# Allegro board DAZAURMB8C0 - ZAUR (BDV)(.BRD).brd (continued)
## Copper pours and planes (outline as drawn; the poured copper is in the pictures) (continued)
GND on SVCC (solid shape): 122.7,125.97 123.57,124.46 125.2,123.87 131.2,123.87 132.83,124.46 133.7,125.97 149.97,125.97 149.97,82.41 140.88,82.41 137.93,85.36 137.94,85.42 137.83,85.69 137.56,85.8 137.5,85.79 133.26,90.03 133.28,90.09 133.29,90.16 133.17,90.43 132.9,90.54 132.84,90.53 132.78,90.52 128.77,94.53 128.68,94.58 128.59,94.6 126.43,94.6 126.33,94.58 126.25,94.53 125.81,94.09 124.58,94.09 124.44,94.25 124.23,94.31 124.03,94.25 123.89,94.09 120.61,94.09 120.47,94.29 120.25,94.36 120.02,94.29 119.88,94.09 119.58,94.09 119.45,94.31 119.2,94.4 118.96,94.31 118.83,94.09 117.9,94.09 117.41,94.58 117.41,95.49 117.47,95.6 117.49,95.72 117.47,95.84 117.41,95.95 117.41,99.81 117.65,99.94 117.74,100.19 117.65,100.44 117.41,100.57 117.41,101.85 117.63,101.98 117.72,102.22 117.63,102.46 117.41,102.59 117.41,103.82 117.65,103.95 117.74,104.2 117.65,104.45 117.41,104.58 117.41,105.78 117.68,105.89 117.79,106.16 117.68,106.43 117.41,106.54 117.41,108.96 117.53,109.09 117.57,109.26 117.47,109.51 117.21,109.61 117.15,109.61 117.09,109.59 116.65,109.96 116.65,125.97
GND on SVCC (solid shape): outline of 153 points within 26.1,28.56 88.83,93.33
GND on IN3 (solid shape): 108.7,41.18 108.7,36.09 108.82,35.96 108.82,33.82 108.63,33.62 108.63,32.75 105.19,32.75 105.19,35.8 106.89,35.8 107.07,35.98 107.07,40.81 107.24,40.98 107.24,41.36 108.51,41.36
GND on IN3 (solid shape): 105.93,125.97 105.97,125.95 105.98,125.92 105.98,125.65 105.93,125.46 105.98,125.28 105.98,122.85 105.97,122.81 105.93,122.8 102.37,122.8 102.34,122.81 102.34,122.82 102.28,122.91 102.2,122.98 102.18,123 102.17,123.02 102.17,123.89 101.62,124.45 101.62,125.36 102.17,125.92 102.18,125.95 102.22,125.97
GND on IN3 (solid shape): 6.12,11.15 6.1,10.85 6.04,10.56 9.28,7.31 9.28,2.46 10.22,1.52 40.42,1.52 40.48,1.53 40.48,3.28 40.51,3.35 40.58,3.38 40.99,3.46 41.32,3.7 41.43,3.73 41.5,3.63 41.5,1.01 41.35,0.65 41,0.51 4,0.51 1.53,1.53 0.51,4 0.51,10.64 3.23,10.64 4.36,10.18 5.11,11.15 5.11,11.92 6.12,11.92
GND on IN3 (solid shape): 6.89,67.99 8.1,67.1 9.43,67.82 10.53,67.82 8.68,66.12 6.31,66.98 3.12,66.98 3.12,62.76 7.57,62.76 8.17,63.21 8.9,63.36 10.42,63.36 12.59,63.68 13.77,61.84 13.77,61.71 12.76,61.71 12.76,61.84 12.01,62.81 10.88,62.35 8.9,62.35 8.44,62.19 8.17,61.79 8.16,61.75 2.31,61.75 2.11,61.95 2.11,67.79 2.31,67.99
GND on IN3 (solid shape): 12.9,88.91 12.31,87.88 11.2,87.48 8.24,87.48 7.62,86.61 6.6,86.28 5.2,86.28 4.18,86.61 3.56,87.48 3.02,87.48 3.02,86.52 4.12,85.42 6.31,85.42 8.62,86.29 10.49,84.69 10.48,84.6 10.39,84.56 9.44,84.56 8.12,85.31 6.89,84.41 2.21,84.41 2.01,84.61 2.01,87.41 0.51,87.41 0.51,88.29 0.71,88.49 4.49,88.49 4.49,88 4.7,87.5 5.2,87.29 6.6,87.29 7.1,87.5 7.31,88 7.31,88.49 11.2,88.49 11.61,88.62 11.87,88.96 12.85,88.96
GND on IN3 (solid shape): 8.17,47.09 8.44,46.69 8.9,46.53 10.88,46.53 12.01,46.07 12.76,47.04 13.77,47.04 12.59,45.2 10.42,45.52 8.9,45.52 8.17,45.67 7.57,46.12 4.26,46.12 4.26,42.76 7.49,42.76 8.05,43.21 8.75,43.36 10.42,43.36 12.54,43.7 13.77,41.95 13.74,41.87 13.67,41.84 12.76,41.84 12.76,41.89 11.99,42.82 10.88,42.35 8.75,42.35 8.34,42.19 8.14,41.79 8.14,41.75 3.25,41.75 3.25,47.13 8.16,47.13
GND on IN3 (solid shape): 9.14,111.72 6.92,111.75 6.44,111.55 5.93,111.48 3.97,111.48 3.54,111.53 3.12,111.67 3.12,104.92 3.56,104.92 4.18,105.79 5.2,106.12 6.6,106.12 7.62,105.79 8.24,104.92 11.2,104.92 11.65,104.86 12.07,104.69 12.07,104.22 11.62,103.77 11.42,103.87 11.2,103.91 7.31,103.91 7.31,104.4 7.1,104.9 6.6,105.11 5.2,105.11 4.7,104.9 4.49,104.4 4.49,103.91 0.71,103.91 0.51,104.11 0.51,105.19 0.51,105.19 2.11,105.19 2.11,111.21 0.51,111.21 0.51,111.21 0.51,112.59 0.71,112.79 3.3,112.79 3.6,112.57 3.97,112.49 5.93,112.49 6.3,112.57 6.61,112.8 6.62,112.81 7.28,112.82 7.3,112.8 8.55,112.55 8.81,113.8 8.84,113.8 9.86,113.8 9.91,113.8
GND on IN3 (solid shape): 13.77,27.04 12.59,25.2 10.42,25.52 8.75,25.52 8.05,25.67 7.49,26.12 1.98,26.12 2.64,25.48 3.04,24.65 2.91,24.34 2.87,24 2.91,23.66 3.04,23.35 2.77,22.71 2.34,22.17 2.77,22.17 3.37,22.54 4.06,22.67 4.13,22.67 4.2,22.67 4.26,22.67 5.59,22.02 6.12,20.65 6.12,19.93 5.11,19.93 5.11,20.65 4.36,21.62 3.23,21.16 0.51,21.16 0.51,22.49 0.6,22.49 2.11,24 0.6,25.51 0.51,25.51 0.51,27.13 8.14,27.13 8.14,27.09 8.34,26.69 8.75,26.53 10.88,26.53 12.01,26.07 12.76,27.04 12.76,27.16 13.77,27.16
GND on IN3 (solid shape): outline of 106 points within 40.61,5.57 224.66,52.31
GND on IN3 (solid shape): outline of 182 points within 0.51,33.92 205.04,127.49
GND on SGND1 (solid shape): outline of 2588 points within 0.51,0.51 224.66,127.49
VDDBT_RTC on TOP (solid shape): outline of 500 points within 94.04,26.28 102.68,51.76
VDDP on TOP (solid shape): 130.49,37.96 130.49,36.69 130.25,36.44 125.3,36.44 125.16,36.58 125.16,37.61 125.46,37.91 127.9,37.91 128.07,38.09 130.36,38.09
VDDP on BOTTOM (solid shape): 129.65,37.97 129.65,37.83 129.93,37.54 129.93,36.71 129.73,36.51 129.42,36.51 129.35,36.58 128.56,36.58 128.48,36.51 127.94,36.51 127.81,36.38 127.81,36.35 127.65,36.18 127.3,36.18 127.29,36.18 127.19,36.18 127.01,36.36 125.3,36.36 125.17,36.49 125.17,36.97 125.32,37.12 125.75,37.12 125.93,37.3 125.93,37.82 126.07,37.96 129.34,37.96 129.37,37.99 129.63,37.99
VDDP on BOTTOM (solid shape): outline of 193 points within 95.31,76.31 105.45,82.28
VDDP on IN3 (solid shape): outline of 2627 points within 103.81,34.17 129.09,79.76
VDDP_S5 on TOP (solid shape): 98.13,28.89 98.13,26.88 97.9,26.66 96.58,26.66 96.49,26.75 96.49,26.76 96.49,27.57 96.48,27.61 96.47,27.65 96.45,27.66 96.45,28.19 96.47,28.21 96.48,28.24 96.49,28.28 96.49,29.09 96.48,29.14 96.45,29.18 96.45,29.2 96.58,29.32 97.69,29.32
VDDP_S5 on BOTTOM (solid shape): 127.95,47.74 127.95,43.93 128.08,43.8 128.93,43.8 129.49,43.24 129.49,38.8 129.49,38.47 129.23,38.21 125.39,38.21 124.78,38.83 124.78,44.69 126.17,46.09 126.17,47.61 126.34,47.77 126.41,47.82 126.47,47.88 127.81,47.88
VDDP_S5 on SVCC (solid shape): outline of 93 points within 96.84,27.55 128.59,49.13
VDDQ_BOOT on TOP (solid shape): 64.41,120.68 64.41,120.4 64.35,120.33 63.78,120.33 63.11,119.66 62.42,119.66 62.38,119.69 62.38,120.45 62.41,120.48 63.56,120.48 63.8,120.72 64.37,120.72
VDDQ_SW on TOP (solid shape): 59.91,124.04 59.91,122.35 60.91,121.35 63.36,121.35 63.4,121.35 63.43,121.35 63.47,121.35 63.51,121.35 66.03,121.35 66.07,121.31 66.07,121.13 65.98,121.04 64.89,121.04 64.76,120.91 63.77,120.91 63.51,120.66 61.16,120.66 61.1,120.6 61.02,120.56 60.99,120.48 60.66,120.16 60,120.16 59.8,119.96 59.8,119.56 59.74,119.5 59.52,119.5 59.31,119.71 59.21,119.89 59.03,119.99 58.45,120.58 57.31,120.58 57.14,120.75 57.14,123.95 57.37,124.19 59.76,124.19
VDDQ_SW_VPP on TOP (solid shape): 64.63,125.67 64.63,123.64 64.39,123.4 64.39,122.4 64.36,122.38 63.8,122.38 63.37,122.81 63.37,123.26 63.4,123.27 63.57,123.41 63.63,123.62 63.57,123.83 63.4,123.97 63.37,123.98 63.37,125.45 63.7,125.77 64.53,125.77
VDDQ_VCC on TOP (solid shape): 69.89,124.48 69.55,124.14 66.22,124.14 66,123.92 65.7,123.92 65.42,123.63 65.41,123.48 65.41,123.45 65.41,123.41 65.42,123.37 65.42,122.97 65.39,122.94 65.39,122.38 65.22,122.38 65.18,122.4 65.17,122.43 65.17,122.94 64.91,122.94 64.91,122.43 64.9,122.4 64.86,122.38 64.72,122.38 64.68,122.4 64.67,122.43 64.67,122.94 64.64,122.94 64.51,123.07 64.51,123.35 64.68,123.52 64.69,123.52 64.76,123.57 64.78,123.64 64.78,124.32 64.78,124.96 64.88,125.06 67.04,125.06 67.08,125.11 69.89,125.11
VDDQ_VLDOIN on TOP (solid shape): 64.38,120.03 64.38,119.57 64.18,119.37 64.16,119.36 63.95,119.27 63.83,119.07 63.82,119.06 63.64,118.88 63.64,118.57 63.63,118.55 63.6,118.49 63.59,118.42 63.59,118.36 63.48,118.25 62.41,118.25 62.37,118.29 62.37,119.06 62.82,119.51 63.14,119.51 63.17,119.54 63.18,119.54 63.22,119.57 63.25,119.61 63.26,119.62 63.77,120.13 64.28,120.13
VDDQ_VTTREF on TOP (solid shape): 67.32,120.18 67.3,120.11 67.29,120.04 67.31,119.91 67.37,119.8 67.37,119.62 67.88,119.11 69.28,119.11 69.4,118.99 69.4,118.51 69.33,118.44 67.74,118.44 66.64,119.54 66.64,120.14 66.62,120.14 66.74,120.26 67.24,120.26
3662AC_CPU_LG1 on BOTTOM (solid shape): 134.8,62.58 135.46,62.58 135.66,62.37 135.66,61.98 135.48,61.8 134.57,61.8 134.49,61.79 134.4,61.71 134.4,61.23 134.12,60.95 132.54,60.95 132.4,61.09 132.4,61.78 133.35,62.72 134.66,62.72
3662AC_CPU_LG2 on BOTTOM (solid shape): 135.48,54.95 135.55,54.95 136.12,54.39 137.24,54.39 137.31,54.32 137.31,53.7 137.25,53.64 135.53,53.64 135.16,54.01 135.16,54.87 135.25,54.95 135.36,54.95
3662AC_CPU_LX1 on TOP (solid shape): 132.33,58.91 132.33,57.65 132.32,57.64 132.32,57.09 132.01,56.78 131.68,56.78 131.41,57.05 131.41,58.92 131.47,58.97 132.26,58.97
3662AC_CPU_LX1 on BOTTOM (solid shape): 132.27,62.21 132.27,60.99 132.49,60.77 133.13,60.77 133.25,60.65 133.25,57.32 133.12,57.19 129.68,57.19 128.67,58.2 128.67,59.43 129.08,59.84 129.28,59.84 129.38,59.94 129.38,60.06 129.35,60.09 129.35,60.16 129.27,60.24 128.75,60.24 128.74,60.24 128.67,60.31 128.67,60.57 128.7,60.58 128.89,60.72 128.97,60.95 128.9,61.17 128.71,61.31 128.67,61.32 128.67,61.97 129.1,62.4 132.08,62.4
3662AC_CPU_LX2 on BOTTOM (solid shape): 135.02,54.58 135.02,53.92 135.47,53.47 136.16,53.47 136.41,53.23 136.41,49.93 135.49,49.01 135.49,48.41 135.35,48.27 134.62,48.27 134.56,48.33 134.56,48.91 131.91,51.57 131.91,52.58 132.01,52.68 132.47,52.68 132.51,52.73 132.51,52.92 132.44,52.99 132.04,52.99 131.91,53.12 131.91,54.47 132.27,54.82 134.78,54.82
3662AC_HG1 on BOTTOM (solid shape): 140.24,60.43 140.24,59.69 139.85,59.3 139.04,59.3 139.01,59.33 139.01,60.08 139.14,60.22 139.57,60.22 139.86,60.51 139.9,60.51 139.94,60.55 140.12,60.55
3662AC_HG2 on BOTTOM (solid shape): 144.21,51.78 144.21,51.25 143.61,50.65 143.26,50.65 142.76,51.15 142.64,51.15 142.53,51.26 142.53,52.04 142.6,52.1 143.88,52.1
3662AC_NB_HG1 on BOTTOM (solid shape): 134.56,70.92 134.56,70.14 134.4,69.98 134.12,69.98 133.61,70.49 133.61,71.29 133.68,71.36 134.11,71.36
3662AC_NB_LG1 on BOTTOM (solid shape): 136.23,66.38 136.23,65.35 136.01,65.14 135.5,65.14 135.45,65.18 135.45,66.12 135.77,66.43 136.18,66.43
3662AC_NB_LX1 on BOTTOM (solid shape): 138.02,76.92 138.02,73.17 138.35,72.84 138.35,71.97 138.58,71.74 139.73,71.74 140.14,71.33 140.14,66.72 140.03,66.61 134.93,66.61 134.7,66.84 134.7,71.08 134.29,71.49 133.55,71.49 133.4,71.34 133.4,70.11 133.28,69.99 129.57,69.99 129.36,70.2 129.36,72.89 129.65,73.19 131.99,73.19 133.17,74.36 133.17,74.6 135.53,76.95 137.99,76.95
3662AM_HG1_GPU on BOTTOM (solid shape): 79.51,106.49 79.51,105.93 79.49,105.92 78.88,105.92 78.83,105.87 78.41,105.87 78.38,105.84 77.56,105.84 77.48,105.91 77.48,106.51 77.59,106.62 79.38,106.62
3662AM_HG1_VDDCI on BOTTOM (solid shape): 79.59,122.36 79.59,121.64 79.39,121.45 77.91,121.45 77.86,121.4 77.86,120.81 77.74,120.69 77.43,120.69 77.34,120.78 77.34,122.36 77.43,122.45 79.5,122.45
3662AM_HG2_GPU on BOTTOM (solid shape): 77.79,99.96 77.81,99.96 77.82,99.95 77.92,99.85 77.92,99.21 77.69,98.98 76.12,98.98 76.03,99.07 76.03,99.85 76.15,99.96
3662AM_LG1_GPU on BOTTOM (solid shape): 85.69,106.18 85.69,105.84 85.69,105.84 85.69,105.64 85.25,105.2 84.94,105.2 84.91,105.23 84.51,105.23 84.08,105.66 83.47,105.66 83.3,105.83 83.3,106.48 85.39,106.48
3662AM_LG1_VDDCI on BOTTOM (solid shape): 79.66,116.59 79.66,116.22 79.66,116.22 79.66,115.5 79.51,115.35 79.29,115.35 79.06,115.57 79.06,115.82 78.85,116.03 78.85,116.67 78.95,116.76 79.49,116.76
3662AM_LG2_GPU on BOTTOM (solid shape): 84.17,99.1 84.17,98.88 83.93,98.64 82.28,98.64 81.74,99.18 81.74,99.81 81.76,99.83 83.44,99.83
3662AM_LX1_GPU on BOTTOM (solid shape): 88.4,110.64 88.4,108.71 88.27,108.58 87.97,108.58 87.89,108.5 87.89,108.4 87.97,108.32 87.97,108.31 88.06,108.31 88.07,108.32 88.49,108.32 88.63,108.18 88.63,106.55 87.88,105.8 86.04,105.8 85.9,105.94 85.9,106.3 85.55,106.65 84.5,106.65 84.18,106.97 84.18,111.02 84.38,111.22 87.81,111.22
3662AM_LX1_VDDCI on TOP (solid shape): 83.96,118.7 83.96,117.19 83.87,117.11 83.07,117.11 82.93,117.24 82.93,118.36 82.93,118.36 82.93,118.73 83.08,118.87 83.78,118.87
3662AM_LX1_VDDCI on BOTTOM (solid shape): 87.71,121.49 87.71,120.63 87.52,120.44 86.74,120.44 86.64,120.34 86.64,120.19 86.74,120.09 87.53,120.09 87.71,119.91 87.71,118.31 86.45,117.05 79.1,117.05 79.09,117.06 79.09,119.8 79.25,119.96 83.09,119.96 83.62,120.49 83.62,121.79 84.23,122.4 86.8,122.4
3662AM_LX2_GPU on BOTTOM (solid shape): 84.07,104.39 84.14,104.38 84.2,104.39 84.28,104.41 84.63,104.41 84.7,104.39 84.77,104.38 84.84,104.39 84.91,104.41 86.45,104.41 87.5,103.36 87.5,101.89 87,101.39 86.51,101.39 86.45,101.33 86.45,101.18 86.51,101.13 87.03,101.13 87.32,100.83 87.34,100.81 87.34,100.79 87.34,100.34 85.36,98.36 85.36,97.94 84.85,97.44 83.83,97.44 83.7,97.56 83.7,98.39 83.78,98.47 84.14,98.47 84.43,98.77 84.43,99.11 83.56,99.99 83.1,99.99 82.71,100.37 82.71,104.12 83,104.41 83.99,104.41
3662AM_UGATE1_GPU on BOTTOM (solid shape): 77.43,108.53 77.43,108.46 77.43,108.4 77.6,108.23 78.03,108.23 78.38,107.88 78.38,107.18 78.37,107.17 77.55,107.17 77.25,107.47 77.25,107.82 76.92,108.15 76.92,108.52 77.07,108.67 77.29,108.67
3662AM_UGATE2_GPU on BOTTOM (solid shape): 75.84,99.98 75.84,98.49 75.66,98.32 75.35,98.32 74.77,98.9 74.77,99.81 75.29,100.34 75.47,100.34
3662AM_UGATE_VDDCI on BOTTOM (solid shape): 77.18,122.15 77.18,120.59 77.04,120.45 76.8,120.45 76.63,120.62 76.62,120.64 76.62,120.66 76.62,121.1 76.53,121.19 76.53,121.35 76.39,121.49 76.08,121.49 76.04,121.52 76.04,122.39 76.16,122.5 76.84,122.5
5213EN_1.8V on TOP (solid shape): 38.88,27.24 39.77,27.24 39.77,26.97 39.74,26.94 38.87,26.94 38.78,26.84 38.78,26.82 38.76,26.78 38.75,26.74 38.75,26.44 38.76,26.41 38.78,26.36 38.78,26.06 39.1,25.74 39.1,25.14 39.29,24.95 39.29,24.36 39.23,24.3 38.67,24.3 38.42,24.55 38.42,27.16 38.51,27.25 38.88,27.25
5213FB_1.8V on TOP (solid shape): 42.52,26.37 42.52,25.81 42.61,25.71 42.67,25.71 42.73,25.64 42.79,25.6 42.86,25.59 42.91,25.59 43.11,25.39 43.11,25.21 43.12,25.15 43.15,25.11 43.16,25.09 43.16,24.98 43.04,24.86 42.31,24.86 42.12,24.67 40.68,24.67 40.54,24.82 40.54,25.35 40.92,25.73 40.92,25.73 41.02,25.8 41.09,25.9 41.11,25.92 41.13,26.01 41.13,26.07 41.13,26.15 41.1,26.23 41.1,26.67 41.18,26.74 42.07,26.74 42.07,26.75 42.14,26.75
5213LX_1.8V on TOP (solid shape): 38.77,27.87 38.88,27.76 38.88,27.74 39.76,27.74 39.8,27.7 39.8,27.48 39.76,27.44 38.47,27.44 38.27,27.24 38.27,24.68 38.06,24.47 37.26,24.47 37.16,24.57 37.16,28.41 37.24,28.5 38.14,28.5
5213LX_VDD08 on TOP (solid shape): 91.6,112.58 91.45,112.43 89.88,112.43 89.8,112.51 89.8,112.94 90.13,113.27 90.13,113.78 90.02,113.88 89.17,113.88 89.17,114.18 90.13,114.18 90.84,114.9 91.6,114.9
24780_DH on BOTTOM (solid shape): 122.3,33.31 122.3,32.8 121.92,32.43 121.24,32.43 121.12,32.55 121.12,32.98 121.5,33.37 122.24,33.37
24780_LX on BOTTOM (solid shape): 125.05,32.62 125.05,31.51 125.16,31.4 125.16,28.88 124.63,28.35 124,28.35 123.53,27.87 123.53,27.06 123.38,26.91 120.71,26.91 119.39,28.23 119.39,32.01 119.64,32.26 122.1,32.26 122.5,32.66 122.5,33.3 122.59,33.39 124.28,33.39
24780_VCC on BOTTOM (solid shape): 131.96,32.94 132.12,32.94 132.62,32.44 132.62,32.35 132.6,32.33 131.76,32.33 131.58,32.52 131.2,32.52 131.14,32.58 130.86,32.58 130.76,32.69 130.76,33.06 130.47,33.35 130.47,34.02 130.56,34.12 130.79,34.12
+APU_VDD_33_S5 on TOP (solid shape): outline of 111 points within 90.8,40.5 91.76,49.26
+G_SEN_PW on BOTTOM (solid shape): outline of 218 points within 63.01,14.26 70.17,20.6
+TYPEC_VBUS on BOTTOM (solid shape): 14.15,23.75 14.15,23.72 14.33,23.55 15.51,23.55 15.66,23.39 15.66,22.96 15.57,22.88 14.63,22.88 14.62,22.88 14.25,22.88 14.25,22.88 13.67,22.88 13.66,22.88 13.29,22.88 13.28,22.88 13.18,22.88 13.1,22.8 12.21,22.8 12.15,22.87 12.15,24.24 12.28,24.37 13.53,24.37
+TYPEC_VBUS on IN2 (solid shape): outline of 220 points within 8.57,19.8 15.05,24.37
+USBPWR0 on TOP (solid shape): 19.56,52.55 19.56,51.19 19.47,51.05 19.45,50.9 19.45,50.23 19.47,50.09 19.53,49.97 19.53,49.76 19.49,49.72 17.69,49.72 17.56,49.85 17.56,52.81 17.79,53.05 19.05,53.05
+USBPWR0 on TOP (solid shape): 20.32,55.11 20.32,54.52 20.06,54.26 19.66,54.26 19.58,54.34 19.47,54.4 19.34,54.42 18.7,54.42 18.67,54.44 18.67,54.67 18.93,54.93 19.37,54.93 19.5,54.96 19.62,55.03 19.81,55.23 20,55.23 20.05,55.23 20.1,55.24 20.19,55.24
+USBPWR0 on BOTTOM (solid shape): 15.56,58.78 15.93,58.78 16.74,57.98 19.29,57.98 20.04,57.23 20.04,55.36 20.25,55.14 20.25,54.32 20.13,54.19 20.13,54.05 20.04,53.96 20.04,50.62 19.39,49.98 17.05,49.98 16.77,50.25 16.77,54.8 16.83,54.85 16.83,55.87 16.44,56.25 16.3,56.25 16.22,56.29 16.21,56.39 16.23,56.46 16.24,56.54 16.13,56.81 15.86,56.92 15.67,56.87 15.53,56.74 15.48,56.69 15.4,56.7 15.33,56.72 15.25,56.73 15.1,56.7 14.98,56.6 14.9,56.57 14.83,56.59 14.28,57.14 14.28,58.66 14.41,58.79 15.56,58.79
+USBPWR1 on BOTTOM (solid shape): 19.3,43.06 19.3,40.6 16.8,38.1 16.74,38.09 16.7,38.07 16.53,37.95 16.45,37.77 16.45,37.75 15.92,37.22 14.39,37.22 14.28,37.33 14.28,39.29 16.3,41.31 16.3,42.21 16.3,42.35 16.3,43.5 16.44,43.63 18.73,43.63
+USBPWR1 on BOTTOM (solid shape): 22.41,57.26 22.41,56.88 22.92,56.37 22.92,54.22 21.27,52.56 20.51,52.56 20.38,52.69 20.38,54.09 20.51,54.22 20.51,55.15 20.52,55.19 20.56,55.2 20.94,55.58 20.56,55.96 20.52,55.98 20.51,56.02 20.51,57.52 20.64,57.64 22.03,57.64
+USBPWR1 on IN2 (solid shape): outline of 721 points within 14.16,37.2 23.56,56.5
+VGA_CORE on TOP (solid shape): outline of 677 points within 87.82,100.11 116.48,112.25
+VGA_CORE on BOTTOM (solid shape): outline of 150 points within 103.66,99.48 116.34,109.56
+VGA_CORE on BOTTOM (solid shape): outline of 462 points within 84.5,91.17 95.85,115.83
+VGA_CORE on SVCC (solid shape): outline of 323 points within 86.68,92.7 116.9,115.43
+VGA_CORE on IN3 (solid shape): outline of 4045 points within 87.47,96.51 115.89,116.11
+VREF_CA0 on TOP (solid shape): 50.73,56.25 50.86,56.12 50.86,54.72 51.89,53.69 51.89,52.71 51.62,52.44 51.62,52.06 51.51,51.94 51.45,51.93 50.48,51.93 50.35,52.06 50.35,55.24 50,55.59 49.97,55.6 49.95,55.64 49.95,56.19 50.06,56.3 50.73,56.3
+VREF_CA1 on TOP (solid shape): 43.87,92.22 43.87,90.87 44.11,90.63 44.11,89.7 44.01,89.59 42.57,89.59 42.24,89.92 42.24,91.4 42.34,91.49 42.55,91.49 43.37,92.32 43.78,92.32
+VREF_CA1 on TOP (solid shape): 29.39,66.46 29.52,66.39 29.65,66.37 29.75,66.38 29.85,66.42 29.86,66.42 30.06,66.42 30.09,66.46 31.38,66.46 31.63,66.2 31.63,64.4 31.56,64.32 31.38,64.32 31.35,64.35 31.35,64.78 31.02,65.11 30.21,65.11 29.86,65.47 28.15,65.47 27.98,65.65 27.98,66.41 28.03,66.46
ADOGND on TOP (solid shape): outline of 615 points within 202.99,29.47 215.45,43.04
ADOGND on BOTTOM (solid shape): 211.68,43.04 211.77,42.98 211.75,42.87 211.36,42.48 211.36,42.33 209.98,40.94 209.73,40.94 209.09,40.31 207.46,39.27 205.79,38.31 205.66,38.31 205.55,38.43 205.55,39.34 205.57,39.35 208.41,41.07 211.09,43.03 211.1,43.04
ADOGND on SGND (solid shape): outline of 116 points within 199.71,19.8 215.45,43.04
ADOGND on IN1 (solid shape): outline of 183 points within 202.99,33.04 215.45,43.04
ADOGND on IN1 (solid shape): outline of 321 points within 203.77,19.8 209.61,31.76
ADOGND on IN2 (solid shape): 206.44,34.57 206.44,34.55 206.44,33.3 206.14,33.01 205.02,33.01 203.69,31.67 203.25,31.67 203,31.92 203,33.2 203.01,33.23 203.01,33.26 203.01,34.37 203.38,34.75 204.02,34.75 204.06,34.78 205.17,34.78 205.26,34.8 205.35,34.86 206.16,34.86
ADOGND on IN2 (solid shape): 215.45,42.81 215.45,38.11 214.83,37.49 213.42,37.49 213.36,37.55 213.36,39.34 212.81,39.88 212.52,39.88 212.43,39.93 212.44,40.04 212.49,40.14 212.51,40.25 212.15,40.6 211.8,40.25 211.81,40.14 211.86,40.04 211.87,39.93 211.78,39.88 208.44,39.88 207.08,39.04 205.7,38.26 205.6,38.27 205.55,38.35 205.55,39.34 205.57,39.35 208.41,41.07 211.09,43.03 211.1,43.04 215.22,43.04
ADOGND on IN2 (solid shape): 206.44,30.47 206.56,30.39 206.69,30.36 206.83,30.39 206.94,30.47 207.44,30.47 207.69,30.21 207.69,27.47 207.65,27.39 207.56,27.38 207.51,27.39 207.45,27.39 207.1,27.04 207.45,26.68 207.51,26.68 207.56,26.7 207.65,26.68 207.69,26.6 207.69,25.97 207.64,25.94 207.59,25.9 207.52,25.87 207.45,25.9 207.33,25.97 207.2,26 206.95,25.9 206.81,25.59 206.74,25.56 205.7,25.56 205.64,25.54 205.56,25.44 205.55,25.39 205.55,24.3 205.08,23.82 205.05,23.78 205.04,23.74 205.04,22.97 205.05,22.92 205.08,22.88 205.2,22.76 205.25,22.73 205.29,22.72 205.68,22.72 205.72,22.73 205.76,22.76 205.98,22.97 206.25,22.97 206.25,21.39 205.38,21.39 204.37,20.37 204.09,20.37 203.77,20.69 203.77,21.65 203.99,21.87 204.01,21.91 204.02,21.96 204.02,21.98 204.02,24.26 204.19,24.37 204.99,24.37 205.04,24.38 205.08,24.41 205.28,24.61 205.31,24.65 205.32,24.7 205.32,25.97 205.51,26.16 205.54,26.2 205.55,26.25 205.55,28.82 205.54,28.86 205.51,28.9 205.33,29.09 205.33,29.72 206.07,30.47
ADOGND on SVCC (solid shape): outline of 116 points within 199.71,19.8 215.45,43.04
ADOGND on IN3 (solid shape): 204.53,34.78 204.62,34.72 204.6,34.61 204.21,34.23 204.21,29.3 204.11,29.2 202.55,29.2 202.45,29.28 202.45,30.29 202.44,30.33 202.42,30.36 202.35,30.43 202.35,31.28 202.37,31.3 202.47,31.33 202.54,31.26 202.59,31.15 202.67,31.07 202.71,30.99 202.68,30.92 202.61,30.8 202.58,30.67 202.94,30.31 203.29,30.67 203.25,30.83 203.15,30.95 203.11,31.03 203.14,31.11 203.21,31.22 203.24,31.36 203.17,31.56 203.01,31.69 203.01,34.55 203.24,34.78
ADOGND on IN3 (solid shape): outline of 231 points within 205.55,32.24 215.45,43.04
ADOGND on SGND1 (solid shape): outline of 116 points within 199.71,19.8 215.45,43.04
BAT-V on BOTTOM (solid shape): outline of 646 points within 95.07,13.85 116.88,25.51
BI on BOTTOM (solid shape): 100.38,22.65 100.38,21.09 100.06,20.77 99.22,20.77 99.12,20.87 99.12,22.1 99.21,22.18 99.34,22.18 99.43,22.15 99.53,22.13 99.8,22.25 99.91,22.52 99.91,22.57 99.89,22.63 99.91,22.72 99.99,22.77 100.27,22.77
G5335-LX on BOTTOM (solid shape): 148.96,71.27 148.96,69.37 148.87,69.28 148.68,69.28 148.62,69.31 148.56,69.33 148.5,69.34 148.45,69.34 148.39,69.33 148.34,69.32 148.29,69.3 148.25,69.27 148.2,69.23 148.17,69.19 148.14,69.14 148.12,69.09 148.1,69.04 148.09,68.99 148.09,68.93 148.1,68.88 148.11,68.83 148.14,68.78 148.16,68.74 148.2,68.7 148.24,68.66 148.28,68.63 148.33,68.61 148.38,68.59 148.43,68.58 148.47,68.58 148.5,68.57 148.53,68.55 148.54,68.52 148.55,68.49 148.55,68.48 148.55,67.11 148.11,66.66 147.32,66.66 147.07,66.41 147.07,65.91 147.06,65.9 144.27,65.9 144.11,66.06 144.11,66.16 143.32,66.16 143.32,66.42 144.11,66.42 144.11,66.66 143.32,66.66 143.32,66.92 146.26,66.92 146.34,67 146.34,67.15 146.84,67.15 146.84,67.94 146.59,67.94 146.59,67.15 146.34,67.15 146.34,68.38 146.74,68.77 146.74,69.24 146.45,69.53 143.99,69.53 142.71,70.8 141.51,70.8 141.42,70.9 141.42,71.58 141.66,71.83 148.4,71.83
G5335-LX-1 on BOTTOM (solid shape): 139.15,45.52 141.29,45.52 141.55,45.26 141.79,45.26 141.85,45.21 141.85,44.34 142.1,44.09 142.6,44.09 142.61,44.08 142.61,41.29 142.45,41.13 142.35,41.13 142.35,40.34 142.09,40.34 142.09,41.13 141.85,41.13 141.85,40.34 141.59,40.34 141.59,43.28 141.51,43.36 140.58,43.36 140.56,43.34 139.17,43.34 138.98,43.15 138.98,42.71 138.73,42.45 138.73,41.05 139.17,40.61 139.17,39.87 139.16,39.86 138.3,39.86 136.93,41.23 136.35,41.23 136.27,41.31 136.27,43.61 141.36,43.61 141.36,43.86 140.58,43.86 140.58,43.61 136.27,43.61 136.27,44.72 137.43,45.88 138.8,45.88
HEPWR on BOTTOM (solid shape): 37.3,122.87 37.38,122.83 37.4,122.74 37.39,122.72 37.39,122.69 37.39,122.49 37.42,122.4 37.51,122.36 37.9,122.36 37.99,122.4 38.02,122.49 38.02,122.69 38.02,122.72 38.01,122.74 38.03,122.83 38.11,122.87 39.89,122.87 40.02,122.74 40.02,121.8 39.91,121.7 39.01,121.7 38.88,121.83 38.46,121.83 38.16,121.53 38.16,121.3 37.96,121.09 37.2,121.09 36.89,121.4 36.89,122.17 36.74,122.32 36.21,122.32 36.12,122.41 36.12,122.76 36.22,122.87
JW5222LX1.5V on TOP (solid shape): 196.63,26.78 196.68,26.73 196.75,26.69 197.04,26.4 197.04,25.03 196.98,24.93 196.87,24.95 196.75,25.03 196.61,25.06 196.34,24.94 196.23,24.67 196.26,24.52 196.35,24.39 196.36,24.38 196.38,24.35 196.38,24.24 196.76,23.86 196.76,23.46 196.66,23.35 196.33,23.35 195.96,23.72 193.84,23.72 193.76,23.8 193.76,24.99 193.79,25.03 193.83,25.09 194,25.26 195.55,25.26 195.77,25.47 195.77,26.66 195.9,26.78
L_SPK+ on TOP (solid shape): 115.97,17.68 115.97,15.69 115.76,15.48 114.96,15.48 114.73,15.72 114.73,17.63 114.86,17.77 115.89,17.77
L_SPK+ on IN3 (solid shape): 115.98,16.09 115.98,13.79 115.84,13.65 114.72,13.65 114.51,13.85 114.51,14.9 114.66,15.05 114.66,15.43 114.73,15.49 114.73,16.04 114.87,16.19 115.88,16.19
L_SPK+ on IN3 (solid shape): outline of 110 points within 202.08,17.36 204.37,22.61
L_SPK+_1 on TOP (solid shape): 116.65,21.13 116.65,19.67 116.01,19.04 116.01,18.4 115.76,18.15 115.12,18.15 115,18.27 115,20.81 115.41,21.22 116.56,21.22
L_SPK+_1 on BOTTOM (solid shape): 116.59,22.27 116.59,19.48 116.39,19.29 115.63,19.29 115.5,19.42 115.5,22.21 115.63,22.34 116.52,22.34
L_SPK- on TOP (solid shape): 117.41,17.64 117.41,15.61 117.28,15.48 116.39,15.48 116.3,15.57 116.3,16.28 116.39,16.37 116.39,17.64 116.52,17.77 117.28,17.77
L_SPK- on IN3 (solid shape): 117.47,15.99 117.47,14.57 117.36,14.46 116.55,14.46 116.29,14.72 116.29,16.03 116.45,16.19 117.27,16.19
L_SPK- on IN3 (solid shape): 202.89,21.66 202.89,21.5 202.5,21.11 202.5,21 202.5,21 202.5,19.96 202.29,19.75 200.94,19.75 200.77,19.92 200.77,19.98 202.38,21.59 202.38,21.72 202.5,21.83 202.72,21.83
L_SPK-_1 on TOP (solid shape): 117.59,21.14 117.59,18.45 117.41,18.27 116.52,18.27 116.39,18.4 116.39,18.96 117,19.56 117,21.1 117.09,21.2 117.54,21.2
L_SPK-_1 on BOTTOM (solid shape): 117.59,22.24 117.59,19.47 117.41,19.29 117.09,19.29 116.96,19.42 116.96,22.26 117.04,22.34 117.49,22.34
PBA_PWR_C on BOTTOM (solid shape): 55.62,22.85 55.62,22.25 55.97,21.91 56.75,21.91 57.02,21.64 57.02,20.85 57.02,20.67 57.1,20.58 57.1,20.2 57.11,20.2 57.11,20.05 55.56,20.05 54.82,20.79 54.82,22.75 55.04,22.97 55.5,22.97
R_SPK+ on TOP (solid shape): 122.62,17.51 122.62,16.12 122.58,16.08 119.61,16.08 119.31,16.38 119.31,17.64 119.44,17.77 122.36,17.77
R_SPK+ on IN3 (solid shape): 123.05,17.82 123.05,17.31 122.74,17 121.52,17 121.31,17.22 121.31,17.62 121.72,18.03 122.84,18.03
R_SPK+ on IN3 (solid shape): 202.63,23.95 202.63,22.55 202.42,22.34 201.86,22.34 200.81,23.39 200.81,24.1 201.07,24.36 202.23,24.36
R_SPK+_1 on TOP (solid shape): 119.76,21.07 119.77,21.07 119.77,19.36 120.2,18.92 120.2,18.27 120.08,18.15 119.31,18.15 119.06,18.4 119.06,21.07 119.19,21.2 119.64,21.2
R_SPK+_1 on BOTTOM (solid shape): 120.2,22.21 120.2,19.54 119.95,19.29 119.14,19.29 118.99,19.44 118.99,22.22 118.99,22.24 119.1,22.36 120.06,22.36
R_SPK- on TOP (solid shape): 118.94,17.64 118.94,16.37 118.93,16.37 118.93,16.26 119.08,16.12 119.08,15.62 118.93,15.48 118.04,15.48 117.79,15.73 117.79,17.64 117.92,17.77 118.81,17.77
R_SPK- on IN3 (solid shape): 119.9,16.7 119.9,15.78 119.8,15.69 117.93,15.69 117.82,15.81 117.82,16.75 117.89,16.82 119.78,16.82
R_SPK- on IN3 (solid shape): outline of 191 points within 196.95,19.39 202.27,22.1
R_SPK-_1 on TOP (solid shape): 118.73,21.14 118.73,21.14 118.73,18.32 118.68,18.27 118.02,18.27 117.92,18.38 117.92,21.02 118.11,21.22 118.66,21.22
R_SPK-_1 on BOTTOM (solid shape): 118.68,22.21 118.68,19.54 118.43,19.29 118.04,19.29 117.94,19.39 117.94,22.28 118,22.34 118.55,22.34
RING2 on BOTTOM (solid shape): 210.54,35.49 210.54,34.45 210.39,34.3 209.36,34.3 209.24,34.41 209.24,35.47 209.35,35.57 210.46,35.57
RING2 on BOTTOM (solid shape): 212.65,40.55 214.02,40.55 214.07,40.5 214.07,39.32 214.02,39.28 211.89,39.28 211.72,39.44 211.72,39.55 213.95,39.55 213.95,39.75 212.65,39.75 212.65,39.55 211.72,39.55 211.72,40.05 213.95,40.05 213.95,40.25 212.65,40.25 212.65,40.05 211.72,40.05 211.72,40.25 212.04,40.57 212.65,40.57
RING2 on IN1 (solid shape): 204.07,32.62 204.07,31.37 203.82,31.12 202.8,31.12 202.65,31.27 202.65,32.01 203.31,32.66 204.03,32.66
RING2 on IN1 (solid shape): outline of 123 points within 207.96,34.28 212.59,40.65
SENSEA on BOTTOM (solid shape): 200.84,31.5 201.14,31.5 201.21,31.44 201.21,30.63 201.04,30.46 201.04,30.25 201.04,30.25 201.04,29.31 200.97,29.24 200.52,29.24 199.71,30.06 199.71,30.61 199.86,30.77 199.9,30.77 199.99,30.73 200.09,30.72 200.47,31.1 200.09,31.48 200.02,31.48 199.96,31.46 199.71,31.46 199.71,32.05 199.76,32.1 200.24,32.1
SLEEVE on BOTTOM (solid shape): 210.49,34.04 210.49,33.25 210.37,33.13 209.4,33.13 209.29,33.23 209.29,34.12 209.3,34.14 210.4,34.14
SLEEVE on BOTTOM (solid shape): 212.65,39.05 213.95,39.05 213.97,39.06 214.02,39.01 214.02,38.75 212.65,38.75 212.65,38.55 214.02,38.55 214.02,38.25 212.65,38.25 212.65,38.05 214.02,38.05 214.02,37.81 213.96,37.75 212.65,37.75 212.65,37.74 212.5,37.74 212.36,37.9 212.15,37.96 212.01,37.93 211.89,37.85 211.82,37.83 211.75,37.86 211.72,37.88 211.72,38.92 211.89,39.09 212.65,39.09
SLEEVE on IN2 (solid shape): 204.57,30.84 204.57,29.55 204.4,29.38 202.83,29.38 202.7,29.52 202.7,30.75 202.86,30.91 204.5,30.91
SLEEVE on IN2 (solid shape): 212.59,39.02 212.59,38.06 212.48,37.94 210.93,37.94 210.69,38.18 210.69,38.84 210.96,39.12 212.5,39.12
SLEEVE on IN2 (solid shape): 209.19,34.32 209.23,34.28 209.28,34.24 209.38,34.14 210.57,34.14 210.62,34.09 210.62,33.39 210.27,33.03 207.46,33.03 207.2,33.29 207.2,34.64 207.5,34.94 208.58,34.94
USBPWRD2 on TOP (solid shape): 215.69,30.37 215.69,27.86 215.61,27.78 214.22,27.78 213.75,28.25 213.75,30.09 214.16,30.5 215.55,30.5
USBPWRD2 on BOTTOM (solid shape): outline of 134 points within 209.66,22.4 215.16,31.1
VA on TOP (solid shape): outline of 205 points within 8.7,114.29 41.43,120.88
VA on BOTTOM (solid shape): 41.67,120.08 41.67,118.91 41.31,118.55 40.91,118.55 40.6,118.86 39.94,118.86 39.84,118.96 39.84,120.23 39.89,120.28 41.46,120.28
VA on BOTTOM (solid shape): outline of 110 points within 8.7,115.7 22.13,119.37
VA on IN1 (solid shape): outline of 171 points within 8.7,115.04 42.12,122.58
VA on IN2 (solid shape): outline of 218 points within 8.7,115.25 42.12,122.29
VA on SVCC (solid shape): 41.59,122.49 41.59,115.92 40.85,115.17 40.83,115.18 40.56,115.06 40.45,114.79 19.62,114.79 19.52,114.77 19.44,114.72 17.36,112.64 14.52,112.64 13.27,113.88 13.19,113.94 13.09,113.96 10.39,113.96 10,114.77 9.33,115.38 9.2,115.47 9.07,115.56 9.07,117.64 9.2,117.73 9.33,117.82 10.03,118.48 10.43,119.37 12.97,119.37 13.57,117.95 15,117.37 15.37,117.4 15.73,117.5 32.66,117.5 34,118.06 34.56,119.4 34.56,122.87 41.22,122.87
VA on IN3 (solid shape): outline of 219 points within 8.7,115.04 41.49,122.43
VA2 on TOP (solid shape): 43.5,122.27 43.5,122.03 44.51,121.02 44.51,120.38 45.01,119.89 45.01,116.85 44.73,116.57 43.75,116.57 43.57,116.39 41.77,116.39 41.72,116.45 41.72,119.75 41.84,119.87 42.73,119.87 42.99,120.13 42.99,120.89 42.35,121.53 42.35,122.37 42.43,122.45 43.32,122.45
VREFC_A0 on TOP (solid shape): 141.17,117.34 141.17,116.65 141.31,116.51 141.31,116.06 141.03,115.78 139.99,115.78 139.86,115.92 139.86,116.61 139.43,117.05 139.43,117.4 139.52,117.5 141.01,117.5
VREFC_A1 on BOTTOM (solid shape): 140.57,83.42 140.57,82.95 140.54,82.87 140.53,82.78 140.59,82.58 140.75,82.45 141.01,82.19 141.01,80.57 141.47,80.11 143.16,80.11 143.16,80.11 143.55,80.11 143.61,80.06 143.61,79.74 143.53,79.67 141.36,79.67 141.31,79.62 140.86,79.62 140.81,79.68 140.74,79.76 140.66,79.82 140.51,79.97 140.51,81.89 140.2,82.21 140.2,83.52 140.27,83.59 140.39,83.59
VREFD1_A0 on TOP (solid shape): 149.17,113.75 149.17,113.54 148.97,113.34 148.97,111.93 148.75,111.71 148.17,111.71 147.61,112.26 147.61,113.52 147.77,113.69 148.46,113.69 148.61,113.83 149.1,113.83
VREFD1_A0 on BOTTOM (solid shape): 147.09,112.92 148.09,112.92 148.25,112.76 148.25,112.57 148.11,112.43 147,112.43 146.57,112.86 146.57,113.12 146.61,113.16 146.85,113.16
VREFD1_A1 on BOTTOM (solid shape): 131.1,90.86 131.1,88.97 131.37,88.7 133.01,88.7 133.99,87.72 133.99,86.85 134.18,86.66 134.18,86.48 134.1,86.41 133.76,86.41 133.6,86.56 133.6,87.43 132.83,88.21 131.07,88.21 130.53,88.75 130.53,90.9 130.58,90.95 131.01,90.95
VREFD2_A0 on BOTTOM (solid shape): 130.78,114.33 130.78,112.68 130.78,112.45 131.12,112.12 133.1,112.12 133.48,112.5 133.48,112.62 133.47,112.62 133.47,112.96 133.79,113.28 134.12,113.28 134.2,113.2 134.2,112.91 134.02,112.74 134.02,112.22 133.45,111.65 130.75,111.65 130.26,112.15 130.26,112.57 130.3,112.61 130.3,114.36 130.32,114.39 130.73,114.39
VREFD2_A1 on BOTTOM (solid shape): 147.59,80.86 147.59,79.8 147.54,79.75 147.07,79.75 147.01,79.8 145.1,79.8 145.04,79.87 145.04,80.18 145.11,80.25 146.81,80.25 146.95,80.38 146.95,80.84 147.12,81.02 147.43,81.02
N17046941 on BOTTOM (solid shape): 106.49,22.63 106.49,22.43 106.49,21.98 105.74,21.23 105.74,20.79 105.69,20.74 105.08,20.74 104.99,20.84 104.99,22.58 105.14,22.73 106.39,22.73
N17047007 on TOP (solid shape): 47.99,120.38 48.81,120.38 48.85,120.38 49.45,120.38 49.48,120.38 50.35,120.38 52.26,118.48 52.51,118.48 52.77,118.22 52.77,115.36 52.85,115.28 52.85,114.6 52.82,114.57 52.48,114.57 52.45,114.57 52.42,114.56 52.22,114.56 52.08,114.7 52.08,114.87 51.27,115.68 51.24,115.71 51.22,115.73 51.09,115.86 50.58,115.86 50.35,115.63 49.99,115.63 49.95,115.64 49.91,115.65 49.85,115.66 49.68,115.62 49.55,115.52 49.54,115.51 49.46,115.47 49.39,115.51 49.38,115.52 49.25,115.62 49.08,115.66 49.06,115.66 48.84,115.57 48.71,115.36 48.7,115.32 47.8,115.32 47.78,115.3 45.91,115.3 45.65,115.56 45.65,116.16 45.78,116.29 45.78,120.26 46.75,121.22 47.15,121.22
N17047104 on TOP (solid shape): 118.51,29.32 118.52,29.32 118.52,28.29 118.67,28.13 120.74,28.13 120.75,28.14 121.21,28.14 121.46,27.89 121.46,27.33 121.28,27.14 120.46,27.14 120.46,27.15 119.37,27.15 118.83,26.6 115.34,26.6 115.14,26.81 115.14,29.21 115.43,29.5 118.33,29.5
N17047104 on BOTTOM (solid shape): 119.22,32.08 119.22,27.55 118.11,26.44 117.75,26.44 116.44,25.14 113.42,25.14 113.31,25.24 113.31,26.63 113.63,26.94 113.63,27.64 113.31,27.95 113.31,28.45 113.4,28.69 113.31,28.93 113.31,29.09 113.4,29.32 113.31,29.56 113.31,31.74 113.75,32.17 119.13,32.17
N17047425 on BOTTOM (solid shape): 104.6,22.93 104.6,20.99 104.36,20.75 103.19,20.75 103.12,20.82 103.12,22.38 103.87,23.13 104.41,23.13
N17047601 on TOP (solid shape): 121.41,29.06 121.41,28.54 121.21,28.34 119.32,28.34 119.26,28.4 119.26,29.17 119.38,29.29 121.17,29.29
N26418322 on BOTTOM (solid shape): 132.22,47.99 133.51,47.99 133.73,47.76 133.73,46.66 133.96,46.43 135.78,46.43 135.8,46.45 136.56,46.45 136.76,46.65 136.76,47.58 136.96,47.79 137.65,47.79 137.85,47.59 137.85,46.47 137.38,46.01 137.38,46.01 136.14,44.77 136.14,44.76 135.78,44.4 135.78,41.2 136.14,40.84 136.84,40.84 138.05,39.64 138.05,38.57 137.95,38.47 131.02,38.47 130.86,38.64 130.01,38.64 129.74,38.91 129.74,40.02 129.84,40.02 130.36,40.37 129.84,40.73 129.74,40.73 129.74,43.35 129.03,44.06 128.63,44.06 128.59,44.09 128.59,47.86 128.72,47.99 131.71,47.99 131.79,48.07 132.14,48.07
N26418727 on BOTTOM (solid shape): 139.22,39.14 139.22,37.24 139.11,37.12 138.3,37.12 138.23,37.2 138.23,39.23 138.25,39.25 139.11,39.25
N28087213 on TOP (solid shape): 38.16,112.51 38.16,111.87 38.03,111.75 27.8,111.75 27.32,111.26 25.36,111.26 25.23,111.39 25.23,112.51 25.49,112.76 37.91,112.76
N28087213 on BOTTOM (solid shape): 25.87,112.61 25.87,111.64 24.74,110.79 23.44,110.14 20.81,109.08 18.86,109.08 18.48,109.46 18.48,110.73 19.75,112 20.03,112 20.74,111.29 21.42,110.93 21.8,110.93 23.36,111.71 23.96,112.13 24.62,112.79 25.69,112.79
N30442033 on TOP (solid shape): 21.34,30.81 21.34,30.57 21.35,30.52 21.38,30.47 21.4,30.46 21.4,30.17 21.39,30.14 21.37,30.07 21.36,29.99 21.37,29.93 21.38,29.87 21.39,29.84 21.25,29.7 21.25,28.76 20.34,28.76 20.14,28.95 20.14,28.96 20.07,29.06 19.97,29.13 19.96,29.14 19.82,29.27 19.75,29.27 19.29,29.73 19.29,29.87 18.98,30.18 18.98,31.08 19.33,31.42 20.73,31.42
N30442033 on BOTTOM (solid shape): 21.52,30.47 21.52,30.31 21.36,29.99 21.52,29.68 21.52,29.23 21.43,29.1 21.4,28.94 21.41,28.86 21.44,28.77 21.45,28.74 21.02,28.31 18.86,28.31 18.73,28.43 18.73,29.88 18.8,29.96 18.85,30.06 18.85,30.08 18.98,30.21 19.75,30.21 20.25,30.72 21.27,30.72
N30442036 on TOP (solid shape): 20.75,27.35 21.25,27.35 21.28,27.32 21.28,25.98 21.27,25.94 21.27,25.89 21.27,25.85 21.28,25.81 21.28,25.6 21.07,25.4 20.04,25.4 19.87,25.56 19.87,25.77 19.86,25.83 19.86,25.99 19.7,25.99 19.64,26 19.34,26 19.28,25.99 17.76,25.99 17.51,26.24 17.51,27.21 17.66,27.36 19.45,27.36 19.59,27.2 19.8,27.14 20,27.2 20.14,27.36 20.52,27.36 20.53,27.36 20.75,27.36
N30442036 on BOTTOM (solid shape): 21.11,27.77 21.11,25.44 21.03,25.36 19.01,25.36 18.6,25.77 18.6,26.26 18.61,26.28 18.63,26.31 18.64,26.35 18.64,27.72 18.63,27.76 18.61,27.8 18.6,27.81 18.6,27.93 18.72,28.04 20.83,28.04
N30568472 on TOP (solid shape): 44.8,19.05 44.8,18.11 44.38,17.69 44.13,17.69 43.7,17.26 43.7,17.01 43.07,16.38 42.75,16.38 42.55,16.58 42.55,19.01 42.74,19.19 44.66,19.19
N31161954 on TOP (solid shape): 154.22,28.11 154.22,27.61 154.24,27.61 154.24,27.04 153.89,26.68 152.24,26.68 151.7,26.15 149.67,26.15 149.54,26.28 149.54,27.58 149.63,27.68 150.65,27.68 151.03,28.05 151.95,28.05 152.21,27.8 152.97,27.8 153.31,28.13 154.19,28.13
N31161997 on TOP (solid shape): 156.91,28.11 156.91,27.93 157.03,27.8 157.54,27.8 157.67,27.67 157.67,27.25 156.78,26.36 156.78,25.13 155.89,25.13 155.82,25.06 154.43,25.06 154.38,25.1 154.38,26.4 154.45,26.47 154.86,26.47 155.15,26.76 155.82,26.76 155.91,26.72 156.01,26.71 156.39,27.09 156.01,27.47 155.94,27.46 155.87,27.44 155.71,27.44 155.64,27.52 155.64,28.13 155.66,28.15 156.86,28.15
N40550359 on BOTTOM (solid shape): 110.82,124.69 111.23,124.69 111.44,124.47 111.44,124.35 111.44,124.09 111.29,123.94 110.67,123.94 110.64,123.95 110.62,123.95 110.23,123.95 110.2,123.95 110.15,123.92 109.67,123.92 109.67,123.93 108.4,123.93 108.4,123.92 107.63,123.92 107.63,123.93 106.37,123.93 106.36,123.94 106.36,124.2 107.63,124.2 107.63,124.21 108.4,124.21 108.4,124.2 109.67,124.2 109.67,124.27 109.71,124.31 109.79,124.36 109.86,124.41 109.97,124.52 110.02,124.59 110.07,124.67 110.1,124.7 110.8,124.7
N43541412 on TOP (solid shape): 149.41,19.93 149.41,19.04 149.29,18.91 148.07,18.91 147.76,18.6 147.76,18.3 147.61,18.15 147.23,18.15 147.13,18.25 147.13,19.54 147.25,19.67 147.89,19.67 148.27,20.05 149.29,20.05
N43605845 on TOP (solid shape): 147.96,14.92 151.17,14.92 151.21,14.91 151.22,14.87 151.22,13.69 151.17,13.63 151.08,13.6 151.01,13.65 150.87,13.78 150.68,13.83 150.41,13.72 150.3,13.45 150.31,13.39 150.32,13.33 150.31,13.24 150.23,13.19 148.58,13.19 148.49,13.24 148.48,13.33 148.5,13.39 148.5,13.45 148.39,13.72 148.12,13.83 147.92,13.77 147.77,13.61 146.91,13.61 146.89,13.64 146.89,14.86 147.04,15.01 147.88,15.01
N45198823 on TOP (solid shape): 63.15,125.5 63.15,123.99 63.12,123.98 62.93,123.84 62.86,123.62 62.93,123.4 63.12,123.26 63.15,123.25 63.15,122.38 63.12,122.34 63,122.22 62.3,122.22 61.99,122.53 61.99,123.06 61.49,123.57 61.49,124.34 61.39,124.45 58.99,124.45 58.88,124.55 58.88,125.65 59.1,125.87 62.78,125.87
N45198823 on BOTTOM (solid shape): 60.44,125.66 60.44,124.94 59.64,124.14 58.22,124.14 58.01,124.35 58.01,125.87 58.07,125.93 60.17,125.93
N45479516 on TOP (solid shape): 199.07,30.82 199.07,30.34 198.78,30.05 196.92,30.05 196.58,29.7 196.58,28.23 196.53,28.18 195.95,28.18 195.9,28.23 195.9,30.82 196.05,30.97 196.86,30.97 197.06,31.18 198.72,31.18
N46807066 on TOP (solid shape): 142.07,78.23 142.11,78.21 142.15,78.2 145.91,78.2 145.95,78.21 145.99,78.23 146,78.24 146.09,78.24 146.99,77.34 148.82,77.34 149.28,76.88 149.28,74.77 149.19,74.68 142.26,74.68 142.26,74.68 141.66,74.68 141.2,75.15 141.2,78.18 141.26,78.24 142.05,78.24
N46807066 on BOTTOM (solid shape): 143.24,77.84 147.85,77.84 148.01,78 148.92,78 149.03,77.9 149.03,75.2 148.83,75 140.35,75 140,75.35 140,77.69 140.47,78.16 142.92,78.16
N46807891 on BOTTOM (solid shape): 106.36,86.6 106.36,86.09 107.12,85.33 109.79,85.33 109.92,85.2 109.92,84.57 109.79,84.44 107.67,84.44 107.67,84.45 107.6,84.52 107.15,84.52 107.08,84.44 103.95,84.44 103.82,84.57 103.82,85.32 103.83,85.33 103.85,85.37 103.86,85.41 103.86,86.76 104.07,86.98 105.98,86.98
N47284656 on TOP (solid shape): 45.48,28.04 45.48,27.9 45.53,27.85 45.53,23.43 45.38,23.28 44.2,23.28 44.18,23.3 44.18,24.57 44.1,24.65 44.1,25.24 44.1,25.25 44.13,25.34 44.13,25.44 44.12,25.48 44.1,25.54 44.1,26.7 43.36,27.44 43.19,27.44 43.16,27.47 42.41,27.47 42.37,27.44 42.07,27.44 42.07,27.44 41.14,27.44 41.14,27.74 42.07,27.74 42.07,27.75 42.23,27.75 42.69,28.21 45.3,28.21
N47284687 on TOP (solid shape): 36.55,28.38 36.55,26.4 36.47,26.32 35.96,26.32 35.68,26.04 35.68,25.33 35.45,25.11 35.4,25.11 35.39,25.12 35.35,25.14 35.3,25.15 34.92,25.15 34.88,25.14 34.84,25.12 34.83,25.11 32.48,25.11 31.9,24.52 30.67,24.52 30.52,24.67 30.52,28.25 30.75,28.47 31.63,28.47 32.34,27.76 34.82,27.76 35.54,28.48 36.45,28.48
N47284767 on TOP (solid shape): 36.78,25.58 36.78,22.76 36.53,22.51 36.25,22.51 35.93,22.82 35.93,23.89 35.99,24 36,24.12 35.99,24.23 35.93,24.34 35.93,25.61 36.01,25.69 36.67,25.69
N48075705 on TOP (solid shape): 194.34,30.59 194.45,30.51 194.58,30.47 194.63,30.46 194.63,30.32 194.6,30.31 194.37,29.96 194.6,29.61 194.63,29.6 194.63,28.26 194.58,28.18 194.49,28.16 194.43,28.18 194.37,28.18 194.16,28.12 194.02,27.96 194.01,27.93 192.85,27.93 192.72,28.05 192.72,30.09 193.23,30.59
N48838349 on BOTTOM (solid shape): 120.63,85.87 120.63,84.81 120.46,84.65 118.98,84.65 118.68,84.95 117.66,84.95 117.54,84.82 116.39,84.82 116.14,84.57 113.98,84.57 113.85,84.7 113.85,85.33 114.11,85.58 115.89,85.58 116.39,86.09 119.06,86.09 119.49,86.52 119.98,86.52
N48842289 on BOTTOM (solid shape): 93.53,90.92 93.53,88.89 93.41,88.76 87.56,88.76 87.44,88.89 87.44,90.03 87.56,90.16 90.74,90.16 91.63,91.05 93.41,91.05
N48842319 on TOP (solid shape): 95.31,93.97 95.31,92.57 95.18,92.44 93.79,92.44 93.66,92.57 93.66,92.8 93.56,92.9 93.15,92.9 92.98,93.08 92.98,93.33 93.08,93.43 93.56,93.43 93.66,93.53 93.66,93.62 93.68,93.65 93.69,93.7 93.69,93.74 94.04,94.09 95.18,94.09
N48842319 on BOTTOM (solid shape): 96.2,93.59 96.2,91.43 95.95,91.17 94.68,91.17 93.66,92.19 93.66,93.59 93.91,93.84 95.95,93.84

Small or netless copper shapes (teardrops, artwork), in the pictures only: 8 on TOP, 70 on BOTTOM, 3 on IN1, 61 on IN2, 1 on IN3

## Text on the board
Ref Des/Silkscreen Bottom: Please do not print out the lines with 0.39mils/0.01mm in width | DAZAURMB8C0 REV:C | MODEL:ZAUR
User.Comments: CR_1_1 | 16x35 | 30x32 | 33x37
Ref Des/Silkscreen Top: Please do not print out the lines with 0.39mils/0.01mm in width | DAZAURMB8C0 | REV:C
User.12: VA | +5V_S5 | +3V_S5 | +1.2VSUS | +1.8V_S5 | GND | +3V | +VDDCR_SOC | +VGA_CORE | +VDDCI | VDDP_S5 | +5V | +VCC_CORE | +5VPCU | ADOGND
User.29: +1.2VSUS | GND | ADOGND
User.30: +1.2VSUS | GND | ADOGND
User.31: ZAUR-MB | DATE | 12/25/19' | PROJECT | LAYER | REV. | B | 8 | BOTTOM | DAZAURMB8B0 | 17.2
User.32: ZAUR-MB | DATE | 12/25/19' | PROJECT | LAYER | REV. | IN1 | B | 3 | DAZAURMB8B0 | 17.2
User.33: ZAUR-MB | DATE | 12/25/19' | PROJECT | LAYER | REV. | IN2 | B | 4 | DAZAURMB8B0 | 17.2
User.34: ZAUR-MB | DATE | 12/25/19' | PROJECT | LAYER | REV. | IN3 | B | 6 | DAZAURMB8B0 | 17.2
User.45: FIGURE | TYPE | Oblong | Rectangle | Circle | SIZE | 43.0x20.0 | 59.0x20.0 | 59.0x28.0 | 63.0x31.0 | 71.0x31.0 | 75.0x39.0 | 91.0x28.0 | 102.0x31.0 | 118.0x20.0 | 252.0x232.0 | 157.0x157.0 | 10.0 | 12.0 | 14.0 | 18.0 | 22.0 | 32.0 | 35.0 | 102.0 | 118.0 | 126.0 | 154.0 | 221.0 | 41.0 | 43.0 | 47.0 | 63.0 | 67.0 | 75.0 | 98.0 | DRILL CHART: TOP to BOTTOM | ALL UNITS ARE IN MILS | PLATED | NON-PLATED | ROTATION | 90.000 | 0.000 | - | QTY | 2 | 6 | 4 | 1 | 33 | 5458 | 9 | 5 | 221 | 40 | 10 | 19 | 18 | 8 | 3 | 5809 | TOTAL HOLES:
